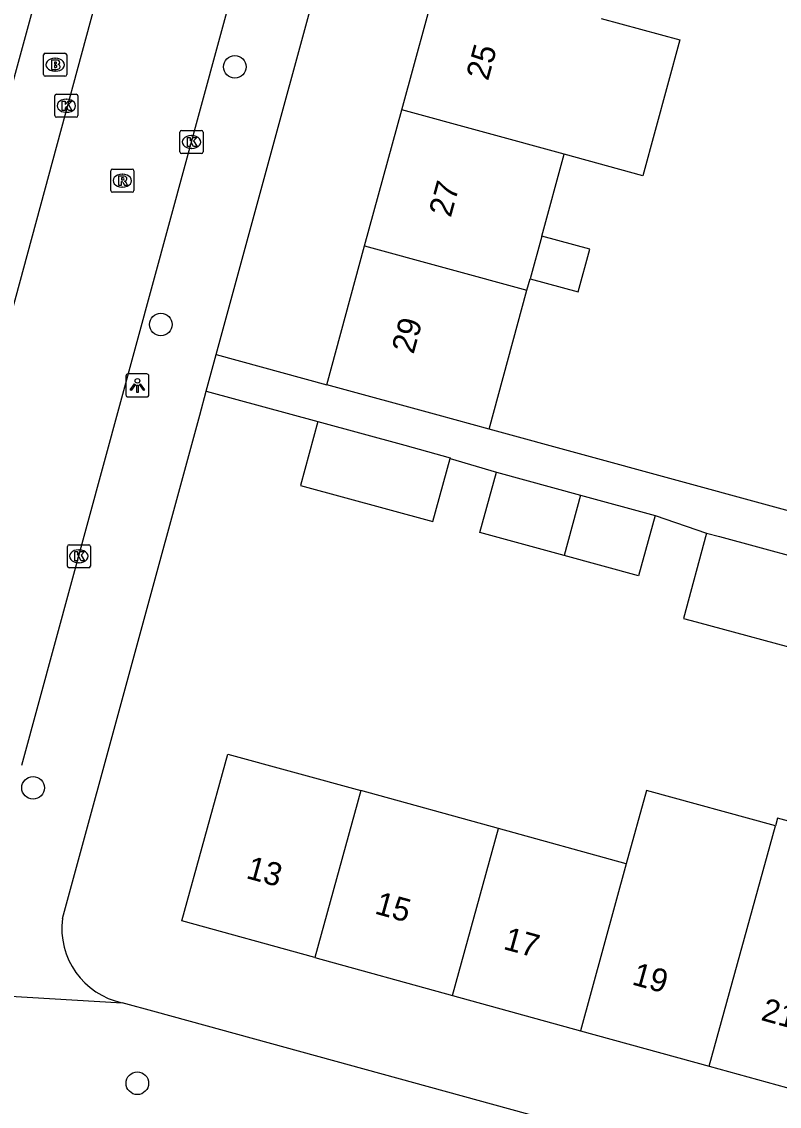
# Model space of a CAD drawing. Extents: x 159822 to 160765, y 380693 to 381634.
# Drawn here: x 160301.88 to 160334.69, y 381019.18 to 381066.14 of the extents above; entities that cross this region are included whole.
import ezdxf

# ---------------------------------------------------------------- set-up
doc = ezdxf.new("R2010")
doc.units = 0
for name, color, linetype in [('IMGEO_Boom', 7, 'Continuous'), ('IMGEO_Brandkraan', 7, 'Continuous'), ('IMGEO_Kolk', 7, 'Continuous'), ('IMGEO_Lichtpunt', 7, 'Continuous'), ('IMGEO_Pand', 7, 'Continuous'), ('IMGEO_Pand_nummerreeks', 7, 'Continuous'), ('IMGEO_Rijbaan_lokaal_open', 7, 'Continuous'), ('IMGEO_Rioolput', 7, 'Continuous'), ('IMGEO_Voetpad_open', 7, 'Continuous')]:
    doc.layers.add(name, color=color, linetype=linetype)

msp = doc.modelspace()

# ---------------------------------------------------------------- linework, layer by layer
at = {"layer": 'IMGEO_Boom'}
for centre in [(160311.115, 381064.184), (160307.913, 381053.025), (160302.376, 381032.966), (160306.892, 381020.175)]:
    msp.add_circle(centre, 0.489, dxfattribs=at)
at = {"layer": 'IMGEO_Brandkraan'}
for p, q in [((160302.831, 381063.849), (160302.831, 381064.701)), ((160302.906, 381064.775), (160303.758, 381064.775)), ((160303.319, 381064.555), (160303.344, 381064.555)), ((160303.832, 381064.701), (160303.832, 381063.849)), ((160303.758, 381063.775), (160302.906, 381063.775)), ((160303.342, 381063.995), (160303.317, 381063.995))]:
    msp.add_line(p, q, dxfattribs=at)
for points in [[(160302.831, 381063.849), (160302.831, 381064.701)], [(160302.906, 381064.775), (160303.758, 381064.775)], [(160303.179, 381064.475), (160303.179, 381064.075), (160303.392, 381064.075)], [(160303.41, 381064.475), (160303.179, 381064.475)], [(160303.832, 381064.701), (160303.832, 381063.849)], [(160303.358, 381064.394), (160303.304, 381064.394), (160303.304, 381064.318)], [(160303.304, 381064.318), (160303.357, 381064.318)], [(160303.366, 381064.242), (160303.304, 381064.242), (160303.304, 381064.161)], [(160303.304, 381064.161), (160303.366, 381064.161)], [(160303.758, 381063.775), (160302.906, 381063.775)]]:
    msp.add_lwpolyline(points, dxfattribs=at)
for centre, radius, start, end in [((160302.908, 381064.699), 0.0765, 91.552, 178.448), ((160302.908, 381064.699), 0.0765, 91.552, 178.448), ((160303.414, 381064.33), 0.145, 59.4692, 91.5367), ((160303.756, 381064.699), 0.0765, 1.552, 88.448), ((160303.756, 381064.699), 0.0765, 1.552, 88.448), ((160303.359, 381064.356), 0.0379, 267.8285, 90.9355), ((160303.367, 381064.201), 0.0404, 269.8759, 90.5077), ((160303.398, 381064.326), 0.251, 268.6676, 293.5347), ((160303.439, 381064.377), 0.0922, 285.5137, 58.1501), ((160303.444, 381064.185), 0.105, 301.3115, 78.989), ((160302.908, 381063.851), 0.0765, 181.552, 268.448), ((160302.908, 381063.851), 0.0765, 181.552, 268.448), ((160303.756, 381063.851), 0.0765, 271.552, 358.448), ((160303.756, 381063.851), 0.0765, 271.552, 358.448)]:
    msp.add_arc(centre, radius, start, end, dxfattribs=at)
for centre, major_axis, ratio, start_param, end_param in [((160303.318, 381064.275), (-0.387, 0.002), 0.722429, 4.712389, 7.853982), ((160303.343, 381064.275), (-0.39, 0.002), 0.717154, 1.570796, 4.712389)]:
    msp.add_ellipse(centre, major_axis=major_axis, ratio=ratio, start_param=start_param, end_param=end_param, dxfattribs=at)
at = {"layer": 'IMGEO_Kolk'}
for p, q in [((160303.317, 381062.073), (160303.317, 381062.925)), ((160303.392, 381062.999), (160304.244, 381062.999)), ((160303.805, 381062.779), (160303.83, 381062.779)), ((160304.318, 381062.925), (160304.318, 381062.073)), ((160303.828, 381062.219), (160303.803, 381062.219)), ((160304.244, 381061.999), (160303.392, 381061.999)), ((160308.737, 381060.503), (160308.737, 381061.355)), ((160308.812, 381061.429), (160309.664, 381061.429)), ((160309.225, 381061.209), (160309.25, 381061.209)), ((160309.738, 381061.355), (160309.738, 381060.503)), ((160309.664, 381060.429), (160308.812, 381060.429)), ((160309.248, 381060.649), (160309.223, 381060.649)), ((160303.861, 381042.567), (160303.861, 381043.419)), ((160303.936, 381043.493), (160304.788, 381043.493)), ((160304.862, 381043.419), (160304.862, 381042.567)), ((160304.349, 381043.273), (160304.374, 381043.273)), ((160304.788, 381042.493), (160303.936, 381042.493)), ((160304.372, 381042.713), (160304.347, 381042.713))]:
    msp.add_line(p, q, dxfattribs=at)
for points in [[(160303.317, 381062.073), (160303.317, 381062.925)], [(160303.392, 381062.999), (160304.244, 381062.999)], [(160303.638, 381062.699), (160303.761, 381062.699), (160303.761, 381062.548), (160303.891, 381062.699), (160304.055, 381062.699), (160303.909, 381062.548), (160304.062, 381062.299), (160303.91, 381062.299), (160303.825, 381062.463), (160303.761, 381062.396), (160303.761, 381062.299), (160303.638, 381062.299), (160303.638, 381062.699)], [(160304.318, 381062.925), (160304.318, 381062.073)], [(160304.244, 381061.999), (160303.392, 381061.999)], [(160308.737, 381060.503), (160308.737, 381061.355)], [(160308.812, 381061.429), (160309.664, 381061.429)], [(160309.738, 381061.355), (160309.738, 381060.503)], [(160309.058, 381061.129), (160309.181, 381061.129), (160309.181, 381060.978), (160309.311, 381061.129), (160309.475, 381061.129), (160309.329, 381060.978), (160309.482, 381060.729), (160309.33, 381060.729), (160309.245, 381060.893), (160309.181, 381060.826), (160309.181, 381060.729), (160309.058, 381060.729), (160309.058, 381061.129)], [(160309.664, 381060.429), (160308.812, 381060.429)], [(160303.861, 381042.567), (160303.861, 381043.419)], [(160303.936, 381043.493), (160304.788, 381043.493)], [(160304.862, 381043.419), (160304.862, 381042.567)], [(160304.182, 381043.193), (160304.305, 381043.193), (160304.305, 381043.042), (160304.435, 381043.193), (160304.599, 381043.193), (160304.453, 381043.042), (160304.606, 381042.793), (160304.454, 381042.793), (160304.369, 381042.957), (160304.305, 381042.89), (160304.305, 381042.793), (160304.182, 381042.793), (160304.182, 381043.193)], [(160304.788, 381042.493), (160303.936, 381042.493)]]:
    msp.add_lwpolyline(points, dxfattribs=at)
for centre, start, end in [((160303.394, 381062.923), 91.552, 178.448), ((160303.394, 381062.923), 91.552, 178.448), ((160304.242, 381062.923), 1.552, 88.448), ((160304.242, 381062.923), 1.552, 88.448), ((160303.394, 381062.075), 181.552, 268.448), ((160303.394, 381062.075), 181.552, 268.448), ((160304.242, 381062.075), 271.552, 358.448), ((160304.242, 381062.075), 271.552, 358.448), ((160308.814, 381061.353), 91.552, 178.448), ((160308.814, 381061.353), 91.552, 178.448), ((160309.662, 381061.353), 1.552, 88.448), ((160309.662, 381061.353), 1.552, 88.448), ((160308.814, 381060.505), 181.552, 268.448), ((160308.814, 381060.505), 181.552, 268.448), ((160309.662, 381060.505), 271.552, 358.448), ((160309.662, 381060.505), 271.552, 358.448), ((160303.938, 381043.417), 91.552, 178.448), ((160303.938, 381043.417), 91.552, 178.448), ((160304.786, 381043.417), 1.552, 88.448), ((160304.786, 381043.417), 1.552, 88.448), ((160303.938, 381042.569), 181.552, 268.448), ((160303.938, 381042.569), 181.552, 268.448), ((160304.786, 381042.569), 271.552, 358.448), ((160304.786, 381042.569), 271.552, 358.448)]:
    msp.add_arc(centre, 0.0765, start, end, dxfattribs=at)
for centre, major_axis, ratio, start_param, end_param in [((160303.804, 381062.499), (-0.387, 0.002), 0.722429, 4.712389, 7.853982), ((160303.829, 381062.499), (-0.39, 0.002), 0.717154, 1.570796, 4.712389), ((160309.224, 381060.929), (-0.387, 0.002), 0.722429, 4.712389, 7.853982), ((160309.249, 381060.929), (-0.39, 0.002), 0.717154, 1.570796, 4.712389), ((160304.348, 381042.993), (-0.387, 0.002), 0.722429, 4.712389, 7.853982), ((160304.373, 381042.993), (-0.39, 0.002), 0.717154, 1.570796, 4.712389)]:
    msp.add_ellipse(centre, major_axis=major_axis, ratio=ratio, start_param=start_param, end_param=end_param, dxfattribs=at)
at = {"layer": 'IMGEO_Lichtpunt'}
for p, q in [((160307.3, 381050.887), (160306.492, 381050.887)), ((160307.3, 381050.887), (160306.492, 381050.887)), ((160306.398, 381050.792), (160306.398, 381049.985)), ((160306.398, 381050.792), (160306.398, 381049.985)), ((160307.394, 381049.985), (160307.394, 381050.792)), ((160307.394, 381049.985), (160307.394, 381050.792)), ((160306.492, 381049.891), (160307.3, 381049.891)), ((160306.492, 381049.891), (160307.3, 381049.891))]:
    msp.add_line(p, q, dxfattribs=at)
for points in [[(160306.772, 381050.456), (160306.811, 381050.428), (160306.623, 381050.166), (160306.585, 381050.193), (160306.772, 381050.456)], [(160306.874, 381050.408), (160306.921, 381050.408), (160306.921, 381050.086), (160306.874, 381050.086), (160306.874, 381050.408)], [(160306.984, 381050.428), (160307.022, 381050.455), (160307.209, 381050.193), (160307.17, 381050.165), (160306.984, 381050.428)]]:
    msp.add_lwpolyline(points, dxfattribs=at)
msp.add_circle((160306.897, 381050.59), 0.0994, dxfattribs=at)
for centre, start, end in [((160306.492, 381050.792), 90, 180), ((160306.492, 381050.792), 90, 180), ((160307.3, 381050.792), 0, 90), ((160307.3, 381050.792), 0, 90), ((160306.492, 381049.985), 180, 270), ((160306.492, 381049.985), 180, 270), ((160307.3, 381049.985), 270, 0), ((160307.3, 381049.985), 270, 360)]:
    msp.add_arc(centre, 0.0946, start, end, dxfattribs=at)
at = {"layer": 'IMGEO_Pand'}
for points in [[(160318.342, 381062.316), (160319.947, 381068.201)], [(160326.977, 381066.284), (160330.388, 381065.353), (160328.783, 381059.468), (160325.372, 381060.398)], [(160316.737, 381056.431), (160318.342, 381062.316)], [(160325.372, 381060.398), (160318.342, 381062.316)], [(160324.407, 381056.86), (160325.372, 381060.398)], [(160324.407, 381056.86), (160323.901, 381055.006)], [(160323.901, 381055.006), (160325.984, 381054.438), (160326.49, 381056.292), (160324.407, 381056.86)], [(160315.097, 381050.418), (160316.737, 381056.431)], [(160316.737, 381056.431), (160323.767, 381054.513)], [(160323.767, 381054.513), (160323.901, 381055.006)], [(160322.127, 381048.501), (160323.767, 381054.513)], [(160322.127, 381048.501), (160319.921, 381049.103), (160315.097, 381050.418)], [(160314.709, 381048.827), (160313.955, 381046.064), (160317.724, 381045.036), (160319.691, 381044.499), (160320.435, 381047.224)], [(160314.709, 381048.827), (160318.478, 381047.799), (160320.445, 381047.262), (160320.435, 381047.224)], [(160325.377, 381043.027), (160321.731, 381044.022), (160322.443, 381046.634)], [(160322.443, 381046.634), (160326.089, 381045.64)], [(160326.089, 381045.64), (160325.377, 381043.027)], [(160326.089, 381045.64), (160329.312, 381044.76)], [(160329.312, 381044.76), (160328.6, 381042.148), (160325.377, 381043.027)], [(160331.54, 381043.994), (160330.542, 381040.299), (160331.1, 381040.148), (160336.223, 381038.763), (160336.308, 381038.74), (160336.554, 381039.651)], [(160331.54, 381043.994), (160332.098, 381043.843), (160337.196, 381042.466)], [(160314.576, 381025.621), (160308.816, 381027.209), (160310.807, 381034.432), (160316.567, 381032.845)], [(160316.567, 381032.845), (160314.576, 381025.621)], [(160322.536, 381031.2), (160316.567, 381032.845)], [(160334.524, 381031.318), (160328.944, 381032.856), (160328.068, 381029.675)], [(160339.087, 381026.638), (160340.057, 381030.161), (160334.618, 381031.659), (160334.524, 381031.318)], [(160320.546, 381023.976), (160322.536, 381031.2)], [(160328.068, 381029.675), (160322.536, 381031.2)], [(160331.657, 381020.914), (160334.524, 381031.318)], [(160328.068, 381029.675), (160326.078, 381022.451)], [(160314.576, 381025.621), (160320.546, 381023.976)], [(160320.546, 381023.976), (160326.078, 381022.451)], [(160326.078, 381022.451), (160331.657, 381020.914)], [(160331.657, 381020.914), (160337.097, 381019.414)]]:
    msp.add_lwpolyline(points, dxfattribs=at)
at = {"layer": 'IMGEO_Rijbaan_lokaal_open'}
for points in [[(160296.519, 381035.423), (160299.893, 381047.861), (160300.877, 381051.49), (160313.515, 381098.085)], [(160318.934, 381096.61), (160301.881, 381033.927)]]:
    msp.add_lwpolyline(points, dxfattribs=at)
at = {"layer": 'IMGEO_Rioolput'}
for p, q in [((160305.742, 381058.83), (160305.742, 381059.682)), ((160305.817, 381059.756), (160306.669, 381059.756)), ((160306.23, 381059.536), (160306.255, 381059.536)), ((160306.743, 381059.682), (160306.743, 381058.83)), ((160306.253, 381058.976), (160306.228, 381058.976)), ((160306.669, 381058.756), (160305.817, 381058.756))]:
    msp.add_line(p, q, dxfattribs=at)
for points in [[(160305.742, 381058.83), (160305.742, 381059.682)], [(160305.817, 381059.756), (160306.669, 381059.756)], [(160306.331, 381059.454), (160306.079, 381059.456), (160306.079, 381059.056)], [(160306.257, 381059.375), (160306.203, 381059.375), (160306.203, 381059.294)], [(160306.743, 381059.682), (160306.743, 381058.83)], [(160306.079, 381059.056), (160306.203, 381059.056), (160306.203, 381059.218), (160306.214, 381059.218)], [(160306.203, 381059.294), (160306.255, 381059.294)], [(160306.261, 381059.189), (160306.332, 381059.056), (160306.472, 381059.056), (160306.407, 381059.182)], [(160306.669, 381058.756), (160305.817, 381058.756)]]:
    msp.add_lwpolyline(points, dxfattribs=at)
for centre, radius, start, end in [((160305.819, 381059.68), 0.0765, 91.552, 178.448), ((160305.819, 381059.68), 0.0765, 91.552, 178.448), ((160306.263, 381059.279), 0.0964, 77.0061, 93.1865), ((160306.277, 381059.336), 0.0378, 276.6634, 79.6772), ((160306.33, 381059.344), 0.109, 350.3612, 89.416), ((160306.328, 381059.344), 0.112, 277.5842, 350.9817), ((160306.667, 381059.68), 0.0765, 1.552, 88.448), ((160306.667, 381059.68), 0.0765, 1.552, 88.448), ((160306.213, 381059.165), 0.0533, 26.0293, 88.6989), ((160306.239, 381059.483), 0.19, 274.7715, 282.9687), ((160306.312, 381059.129), 0.108, 29.5134, 73.7905), ((160305.819, 381058.832), 0.0765, 181.552, 268.448), ((160305.819, 381058.832), 0.0765, 181.552, 268.448), ((160306.667, 381058.832), 0.0765, 271.552, 358.448), ((160306.667, 381058.832), 0.0765, 271.552, 358.448)]:
    msp.add_arc(centre, radius, start, end, dxfattribs=at)
for centre, major_axis, ratio, start_param, end_param in [((160306.229, 381059.256), (-0.387, 0.002), 0.722429, 4.712389, 7.853982), ((160306.254, 381059.256), (-0.39, 0.002), 0.717154, 1.570796, 4.712389)]:
    msp.add_ellipse(centre, major_axis=major_axis, ratio=ratio, start_param=start_param, end_param=end_param, dxfattribs=at)
at = {"layer": 'IMGEO_Voetpad_open'}
for points in [[(160310.308, 381051.724), (160323.013, 381098.308)], [(160309.076, 381091.342), (160299.133, 381054.896)], [(160309.877, 381050.145), (160310.308, 381051.724)], [(160310.308, 381051.724), (160315.097, 381050.418)], [(160303.649, 381027.31), (160309.594, 381049.106), (160309.877, 381050.145)], [(160309.877, 381050.145), (160314.709, 381048.827)], [(160342.788, 381045.273), (160342.167, 381043.032), (160322.127, 381048.501)], [(160320.435, 381047.224), (160322.443, 381046.634)], [(160329.312, 381044.76), (160331.54, 381043.994)], [(160299.204, 381024.077), (160306.239, 381023.664)], [(160365.368, 381007.43), (160363.438, 381007.96), (160307.725, 381023.254), (160306.239, 381023.664)]]:
    msp.add_lwpolyline(points, dxfattribs=at)
msp.add_arc((160306.904, 381026.879), 3.283, 172.4571, 258.3204, dxfattribs=at)

# ---------------------------------------------------------------- texts
at = {"layer": 'IMGEO_Pand_nummerreeks'}
for s, rotation, p in [('25', 74.7455, (160322.078, 381063.55)), ('27', 74.7481, (160320.464, 381057.632)), ('29', 74.7455, (160318.851, 381051.716)), ('13', 344.5906, (160311.561, 381029.067)), ('15', 344.5906, (160317.13, 381027.532)), ('17', 344.5906, (160322.7, 381025.997)), ('19', 344.5906, (160328.269, 381024.462)), ('21', 344.5906, (160333.859, 381022.921))]:
    msp.add_text(s, height=1, rotation=rotation, dxfattribs=at).set_placement(p)

doc.saveas('drawing.dxf')
